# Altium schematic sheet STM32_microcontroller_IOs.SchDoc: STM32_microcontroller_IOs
size A3; Date: Not used; ApprovedBy: Not used; CheckedBy: Not used; Author: Not used; CompanyName: STMicroelectronics; DrawnBy: Not used; Engineer: Not used; Organization: Not used; Address1: Not used; Address2: Not used; Address3: Not used; Address4: Not used; DocumentNumber: Not used; Revision: Not used; SheetNumber: 3; SheetTotal: 12
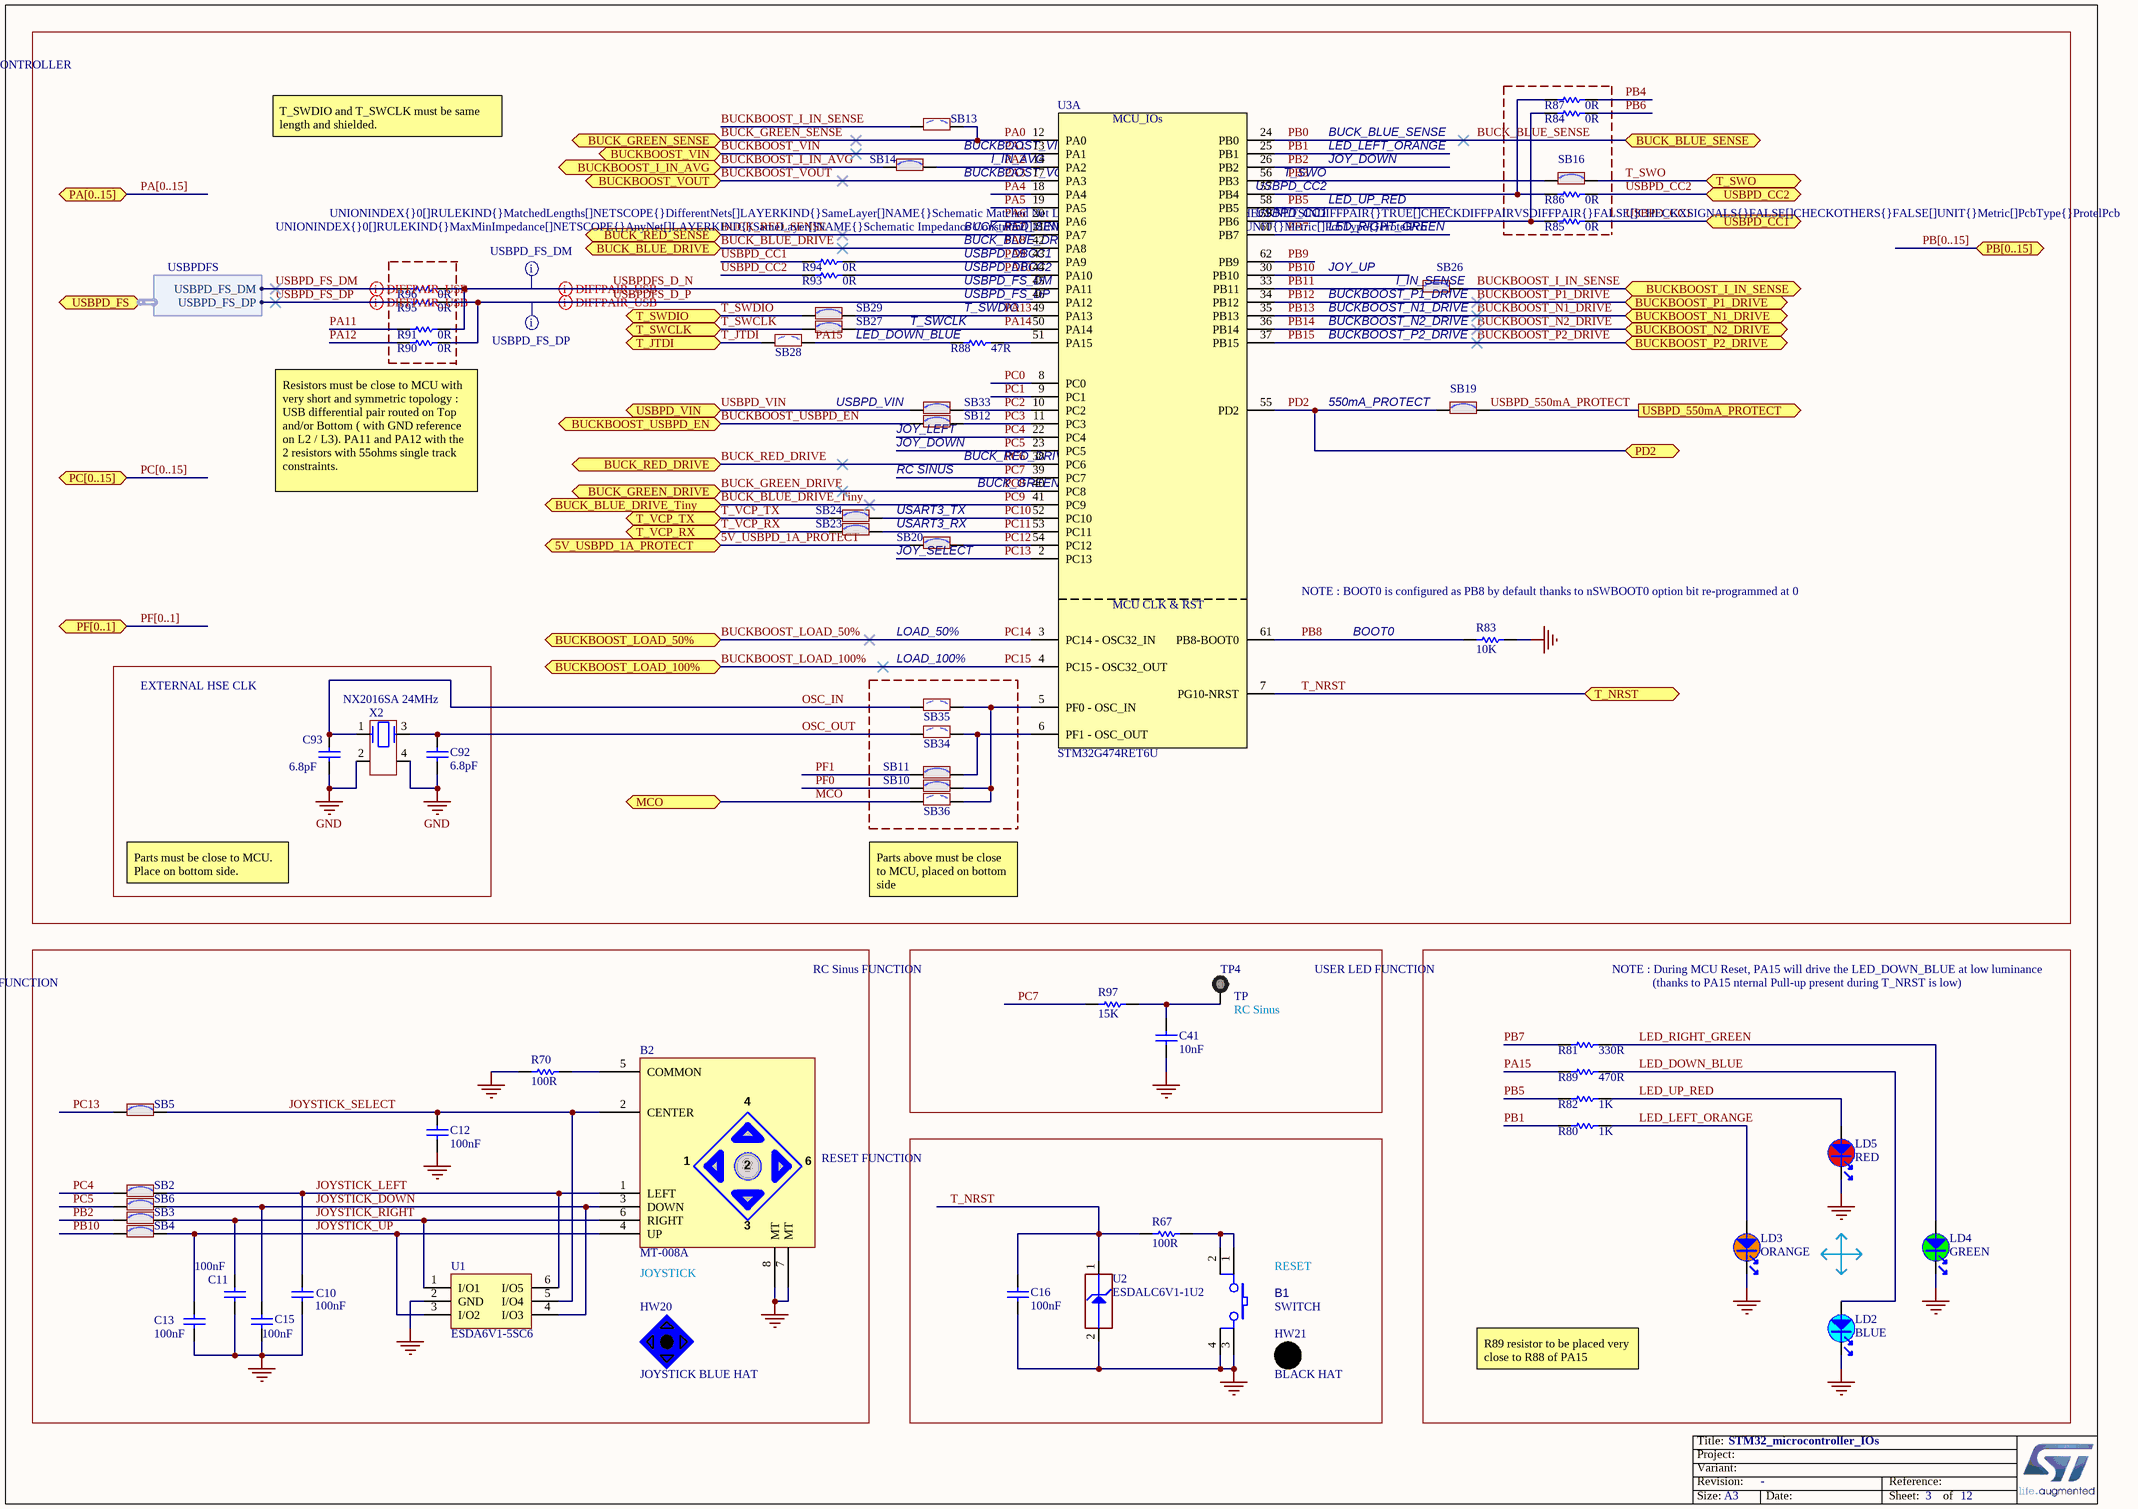
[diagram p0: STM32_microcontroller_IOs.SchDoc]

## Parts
B1  value SWITCH  [SWI_WEALTHMETAL_TD-0341_4P_BLACK]
B2  value MT-008A  [SWI_XIEJIA_MT-008A_6P]
C10  value 100nF  [C0402]
C11  value 100nF  [C0402]
C12  value 100nF  [C0402]
C13  value 100nF  [C0402]
C15  value 100nF  [C0402]
C16  value 100nF  [C0402]
C41  value 10nF  [C0603]
C92  value 6.8pF  [C0402]
C93  value 6.8pF  [C0402]
HW20  value JOYSTICK BLUE HAT  (hidden comment: JOYSTICK_BLUE_HAT)  (mechanical)
HW21  value BLACK HAT  (mechanical)
LD2  value BLUE  [LED_0603_SMD-B_BLUE_H0P4]
LD3  value ORANGE  [LED_0603_ORANGE_H0P4]
LD4  value GREEN  [LED_0603_GREEN]
LD5  value RED  [LED_0603_RED]
R67  value 100R  [R0603]
R70  value 100R  [R0603]
R80  value 1K  [R0603]
R81  value 330R  [R0603]
R82  value 1K  [R0603]
R83  value 10K  [R0603]
R84  value 0R  [R0402]
R85  value 0R  [R0402]
R86  value 0R  [R0402]
R87  value 0R  [R0402]
R88  value 47R  [R0402]
R89  value 470R  [R0603]
R90  value 0R  [R0402]
R91  value 0R  [R0402]
R93  value 0R  [R0402]
R94  value 0R  [R0402]
R95  value 0R  [R0402]
R96  value 0R  [R0402]
R97  value 15K  [R0603]
SB2  (no value)  [SOLDER-BRIDGE_R0603-0R]
SB3  (no value)  [SOLDER-BRIDGE_R0603-0R]
SB4  (no value)  [SOLDER-BRIDGE_R0603-0R]
SB5  (no value)  [SOLDER-BRIDGE_R0603-0R]
SB6  (no value)  [SOLDER-BRIDGE_R0603-0R]
SB10  (no value)  [SOLDER-BRIDGE_R0603-0R]
SB11  (no value)  [SOLDER-BRIDGE_R0603-0R]
SB12  (no value)  [SOLDER-BRIDGE_R0603-0R]
SB13  (no value)  [SOLDER-BRIDGE_R0603-0R]
SB14  (no value)  [SOLDER-BRIDGE_R0603-0R]
SB16  (no value)  [SOLDER-BRIDGE_R0603-0R]
SB19  (no value)  [SOLDER-BRIDGE_R0603-0R]
SB20  (no value)  [SOLDER-BRIDGE_R0603-0R]
SB23  (no value)  [SOLDER-BRIDGE_R0603-0R]
SB24  (no value)  [SOLDER-BRIDGE_R0603-0R]
SB26  (no value)  [SOLDER-BRIDGE_R0603-0R]
SB27  (no value)  [SOLDER-BRIDGE_R0603-0R]
SB28  (no value)  [SOLDER-BRIDGE_R0603-0R]
SB29  (no value)  [SOLDER-BRIDGE_R0603-0R]
SB33  (no value)  [SOLDER-BRIDGE_R0603-0R]
SB34  (no value)  [SOLDER-BRIDGE_R0603-0R]
SB35  (no value)  [SOLDER-BRIDGE_R0603-0R]
SB36  (no value)  [SOLDER-BRIDGE_R0603-0R]
TP4  value TP  [TP_PTH_1MM_2MM]
U1  value ESDA6V1-5SC6  [ESD_SOT23-6L]
U2  value ESDALC6V1-1U2  [ESD_ST0201]
U3  STM32G474RET6U  [ICC_LQFP64_10X10_P050]  (part A of 2)
X2  value NX2016SA 24MHz  [CRY_NX2016SA_4P]

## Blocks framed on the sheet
EXTERNAL HSE CLK: C92 C93 X2
LOAD_100%: SB10 SB11 SB34-SB36
USER LED FUNCTION: LD2-LD5 R80-R82 R89

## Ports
5V_USBPD_1A_PROTECT, BUCK_BLUE_DRIVE, BUCK_BLUE_DRIVE_Tiny, BUCK_BLUE_SENSE, BUCK_GREEN_DRIVE, BUCK_GREEN_SENSE, BUCK_RED_DRIVE, BUCK_RED_SENSE, BUCKBOOST_I_IN_AVG, BUCKBOOST_I_IN_SENSE, BUCKBOOST_LOAD_50%, BUCKBOOST_LOAD_100%, BUCKBOOST_N1_DRIVE, BUCKBOOST_N2_DRIVE, BUCKBOOST_P1_DRIVE, BUCKBOOST_P2_DRIVE, BUCKBOOST_USBPD_EN, BUCKBOOST_VIN, BUCKBOOST_VOUT, MCO, PA[0..15] (bidir), PB[0..15] (bidir), PC[0..15] (bidir), PD2, PF[0..1] (bidir), T_JTDI, T_NRST, T_SWCLK, T_SWDIO, T_SWO, T_VCP_RX, T_VCP_TX, USBPD_550mA_PROTECT, USBPD_CC1, USBPD_CC2, USBPD_FS (harness USBPDFS), USBPD_VIN

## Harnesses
USBPDFS: USBPD_FS_DM, USBPD_FS_DP

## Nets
GND: B1.3 B1.4 B2.7(MT) B2.8(MT) C10.1 C11.1 C12.1 C13.1 C15.1 C16.1 C41.1 C92.1 C93.1 LD2.2 LD3.2 LD4.2 LD5.2 R70.1 R83.1 U1.2(GND) U2.2(GND) X2.2 X2.4
5V_USBPD_1A_PROTECT: SB20.1 ; port 5V_USBPD_1A_PROTECT
BUCK_BLUE_DRIVE: U3.42(PA8) ; port BUCK_BLUE_DRIVE  [also labelled PA8]
BUCK_BLUE_DRIVE_Tiny: U3.41(PC9) ; port BUCK_BLUE_DRIVE_Tiny  [also labelled PC9]
BUCK_BLUE_SENSE: U3.24(PB0) ; port BUCK_BLUE_SENSE  [also labelled PB0]
BUCK_GREEN_DRIVE: U3.40(PC8) ; port BUCK_GREEN_DRIVE  [also labelled PC8]
BUCK_GREEN_SENSE: SB13.2 U3.12(PA0) ; port BUCK_GREEN_SENSE  [also labelled PA0]
BUCK_RED_DRIVE: U3.38(PC6) ; port BUCK_RED_DRIVE  [also labelled PC6]
BUCK_RED_SENSE: U3.21(PA7) ; port BUCK_RED_SENSE  [also labelled PA7]
BUCKBOOST_I_IN_AVG: SB14.1 ; port BUCKBOOST_I_IN_AVG
BUCKBOOST_I_IN_SENSE: SB13.1 SB26.2 ; port BUCKBOOST_I_IN_SENSE
BUCKBOOST_LOAD_50%: U3.3(PC14_-_OSC32_IN) ; port BUCKBOOST_LOAD_50%  [also labelled PC14]
BUCKBOOST_LOAD_100%: U3.4(PC15_-_OSC32_OUT) ; port BUCKBOOST_LOAD_100%  [also labelled PC15]
BUCKBOOST_N1_DRIVE: U3.35(PB13) ; port BUCKBOOST_N1_DRIVE  [also labelled PB13]
BUCKBOOST_N2_DRIVE: U3.36(PB14) ; port BUCKBOOST_N2_DRIVE  [also labelled PB14]
BUCKBOOST_P1_DRIVE: U3.34(PB12) ; port BUCKBOOST_P1_DRIVE  [also labelled PB12]
BUCKBOOST_P2_DRIVE: U3.37(PB15) ; port BUCKBOOST_P2_DRIVE  [also labelled PB15]
BUCKBOOST_USBPD_EN: SB12.1 ; port BUCKBOOST_USBPD_EN
BUCKBOOST_VIN: U3.13(PA1) ; port BUCKBOOST_VIN  [also labelled PA1]
BUCKBOOST_VOUT: U3.17(PA3) ; port BUCKBOOST_VOUT  [also labelled PA3]
JOYSTICK_DOWN: B2.3(DOWN) C15.2 SB6.2 U1.4(I/O3)
JOYSTICK_LEFT: B2.1(LEFT) C10.2 SB2.1 U1.6(I/O5)
JOYSTICK_RIGHT: B2.6(RIGHT) C11.2 SB3.1 U1.1(I/O1)
JOYSTICK_SELECT: B2.2(CENTER) C12.2 SB5.2 U1.5(I/O4)
JOYSTICK_UP: B2.4(UP) C13.2 SB4.1 U1.3(I/O2)
LED_DOWN_BLUE: LD2.1 R89.2
LED_LEFT_ORANGE: LD3.1 R80.1
LED_RIGHT_GREEN: LD4.1 R81.1
LED_UP_RED: LD5.1 R82.1
MCO: SB36.1 ; port MCO
OSC_IN: C93.2 SB35.1 X2.1
OSC_OUT: C92.2 SB34.1 X2.3
PA2: SB14.2 U3.14(PA2)
PA4: U3.18(PA4)
PA5: U3.19(PA5)
PA6: U3.20(PA6)
PA9: R94.2 U3.43(PA9)
PA10: R93.2 U3.44(PA10)
PA11: R91.1
PA12: R90.1
PA13: SB29.2 U3.49(PA13)
PA14: SB27.2 U3.50(PA14)
PA15: R88.1 R89.1 SB28.2
PB1: R80.2 U3.25(PB1)
PB2: SB3.2 U3.26(PB2)
PB3: SB16.1 U3.56(PB3)
PB4: R87.2
PB5: R82.2 U3.58(PB5)
PB6: R84.2
PB7: R81.2 U3.60(PB7)
PB8: R83.2 U3.61(PB8-BOOT0)
PB9: U3.62(PB9)
PB10: SB4.2 U3.30(PB10)
PB11: SB26.1 U3.33(PB11)
PC0: U3.8(PC0)
PC1: U3.9(PC1)
PC2: SB33.2 U3.10(PC2)
PC3: SB12.2 U3.11(PC3)
PC4: SB2.2 U3.22(PC4)
PC5: SB6.1 U3.23(PC5)
PC7: R97.1 U3.39(PC7)
PC10: SB24.2 U3.52(PC10)
PC11: SB23.2 U3.53(PC11)
PC12: SB20.2 U3.54(PC12)
PC13: SB5.1 U3.2(PC13)
PD2: SB19.1 U3.55(PD2) ; port PD2
PF0: SB10.1
PF1: SB11.1
T_JTDI: SB28.1 ; port T_JTDI
T_NRST: C16.2 R67.1 U2.1(IO1) U3.7(PG10-NRST) ; port T_NRST
T_SWCLK: SB27.1 ; port T_SWCLK
T_SWDIO: SB29.1 ; port T_SWDIO
T_SWO: SB16.2 ; port T_SWO
T_VCP_RX: SB23.1 ; port T_VCP_RX
T_VCP_TX: SB24.1 ; port T_VCP_TX
USBPD_550mA_PROTECT: SB19.2 ; port USBPD_550mA_PROTECT
USBPD_CC1: R85.2 R94.1 ; port USBPD_CC1
USBPD_CC2: R86.2 R93.1 ; port USBPD_CC2
USBPD_FS_DM: R96.1 ; port USBPD_FS.USBPD_FS_DM
USBPD_FS_DP: R95.1 ; port USBPD_FS.USBPD_FS_DP
USBPD_VIN: SB33.1 ; port USBPD_VIN
USBPDFS_D_N: R91.2 R96.2 U3.45(PA11)
USBPDFS_D_P: R90.2 R95.2 U3.46(PA12)
NetB1_1: B1.1 B1.2 R67.2
NetB2_5: B2.5(COMMON) R70.2
NetC41_2: C41.2 R97.2 TP4.1
NetR84_1: R84.1 R85.1 U3.59(PB6)
NetR86_1: R86.1 R87.1 U3.57(PB4)
NetR88_2: R88.2 U3.51(PA15)
NetSB10_2: SB10.2 SB35.2 SB36.2 U3.5(PF0_-_OSC_IN)
NetSB11_2: SB11.2 SB34.2 U3.6(PF1_-_OSC_OUT)

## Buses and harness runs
bus PA[0..15] = port PA[0..15]
bus PB[0..15] = port PB[0..15]
bus PC[0..15] = port PC[0..15]
bus PF[0..1] = port PF[0..1]

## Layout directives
differential pair; rule Impedance Constraint [Min = 85.00    Max = 95.00    ]: USBPD_FS_DM, USBPD_FS_DP, USBPDFS_D_N, USBPDFS_D_P
rule Undefined; rule Matched Net Lengths [Tolerance = 0.2mm]; rule Impedance Constraint [Min = 85.00    Max = 95.00    ]: USBPDFS_D_N, USBPDFS_D_P

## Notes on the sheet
- MICROCONTROLLER
- T_SWDIO and T_SWCLK must be same length and shielded.
- BUCKBOOST_VIN
- (near SB14) BUCKBOOST_VOUT
- I_IN_AVG
- T_SWO
- LED_LEFT_ORANGE
- JOY_DOWN
- BUCK_BLUE_SENSE
- BUCK_RED_SENSE
- BUCK_BLUE_DRIVE
- USBPD_CC2
- USBPD_CC1
- LED_UP_RED
- LED_RIGHT_GREEN
- (near R88) T_SWDIO
- USBPD_DBCC1
- USBPD_DBCC2
- USBPD_FS_DM
- USBPD_FS_DP
- JOY_UP
- (near SB26) BUCKBOOST_P1_DRIVE
- (near SB26) BUCKBOOST_N1_DRIVE
- (near SB26) I_IN_SENSE
- LED_DOWN_BLUE
- (near R88) T_SWCLK
- (near SB26) BUCKBOOST_P2_DRIVE
- (near SB26) BUCKBOOST_N2_DRIVE
- USBPD_VIN
- (near SB12) JOY_LEFT
- (near SB12) JOY_DOWN
- (near SB19) 550mA_PROTECT
- Resistors must be close to MCU with very short and symmetric topology : USB differential pair routed on Top and/or Bottom ( with GND reference on L2 / L3). PA11 and PA12 with the 2 resistors with 55ohms single track constraints.
- USART3_TX
- RC SINUS
- BUCK_RED_DRIVE
- BUCK_GREEN_DRIVE
- (near SB20) USART3_RX
- (near SB20) JOY_SELECT
- LOAD_50%
- NOTE : BOOT0 is configured as PB8 by default thanks to nSWBOOT0 option bit re-programmed at 0
- (near R83) BOOT0
- Parts must be close to MCU. Place on bottom side.
- Parts above must be close to MCU, placed on bottom side
- JOYSTICK FUNCTION
- RC Sinus FUNCTION
- NOTE : During MCU Reset, PA15 will drive the LED_DOWN_BLUE at low luminance
- (thanks to PA15 nternal Pull-up present during T_NRST is low)
- (near TP4) RC Sinus
- RESET FUNCTION
- JOYSTICK
- (near B1) RESET
- R89 resistor to be placed very close to R88 of PA15

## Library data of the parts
B1 = MCD-00001: Non-Open Push-Button 0.1A 24V BLACK; Manufacturer_Part_Number: TD-0341; Manufacturer: WEALTHMETAL; Part_Type: Misc; Provided_By: SUBCO
B2 = MCD-00132: Joystick, 4 dir, 1 OK; Part_Type: Misc; Manufacturer: XIEJIA Electronics; Provided_By: SUBCO
C10-C13 C15 C16 = MCD-00102: Capacitor, MLCC, 100nF, 16V, X7R, 10%, 0402, T=0,5mm; Manufacturer_Part_Number: CC0402KRX7R7BB104; Manufacturer: YAGEO; Alternate_Manufacturer_Part_Number: GCM155R71C104KA55D; Alternate_Manufacturer: MURATA; Provided_By: SUBCO
C41 = MCD-01007: Capacitor, MLCC, 10nF, 16V, X7R, 10%, 0603, T=0.8mm; Manufacturer_Part_Number: CC0603KRX7R7BB103; Manufacturer: YAGEO; Provided_By: SUBCO
C92 C93 = MCD-00674: Capacitor, MLCC, 6.8pF, 50V, NPO, +-0.25pF, 0402, T=0.5mm; Manufacturer_Part_Number: CC0402CRNPO9BN6R8; Manufacturer: YAGEO; Provided_By: SUBCO
HW20 = MCD-01337: Joystick Blue Hat; Part_Type: Mechanical; Manufacturer_Part_Number: PB-504; Manufacturer: JIUBABA; Provided_By: SUBCO
HW21 = MCD-00635: Black Hat for switch TD0341X-G01-BLA; Part_Type: Mechanical; Manufacturer_Part_Number: 988.16.09.3.00003_SH-517; Manufacturer: JIUBABA; Provided_By: SUBCO
LD2 = MCD-01131: LED Blue, 0603 SMD, Forward Voltage Min=2,8V, Max=3,1V; Part_Type: Display; Manufacturer_Part_Number: 19-217-BHC-ZL1M2RY-3T; Manufacturer: EVERLIGHT; Provided_By: SUBCO
LD3 = MCD-00321: LED, Orange, 0603; Part_Type: Display; Manufacturer_Part_Number: 19-217/S2C-AM2N2VY/3T; Manufacturer: EVERLIGHT; Provided_By: SUBCO
LD4 = MCD-00050: LED, Green, 0603; Manufacturer_Part_Number: 19-213SYGC/S530-E2/TR8; Manufacturer: EVERLIGHT; Part_Type: Display; Provided_By: SUBCO
LD5 = MCD-00049: LED, Red, 0603; Part_Type: Display; Manufacturer_Part_Number: 19-213-R6C-AP1Q2B/3T; Manufacturer: EVERLIGHT; Provided_By: SUBCO
R67 R70 = MCD-00224: Resistor,100R,0603,1%,1/10W; Manufacturer_Part_Number: RC0603FR-07100RL; Manufacturer: YAGEO; Provided_By: SUBCO
R80 R82 = MCD-00070: Resistor,1K,0603,1%,1/10W; Manufacturer_Part_Number: RC0603FR-071KL; Manufacturer: YAGEO; Provided_By: SUBCO
R81 = MCD-00197: Resistor,330R,0603,1%,1/10W; Manufacturer_Part_Number: RC0603FR-07330RL; Manufacturer: YAGEO; BMS_Part_Number: 9129729; Provided_By: SUBCO
R83 = MCD-00220: Resistor,10K,0603,1%,1/10W; Manufacturer_Part_Number: RC0603FR-0710KL; Manufacturer: YAGEO; Provided_By: SUBCO
R84-R87 R90 R91 R93-R96 = MCD-00052: Resistor,0R,0402,5%,1/16W; Manufacturer_Part_Number: RC0402JR-070RL; Manufacturer: YAGEO; Provided_By: SUBCO
R88 = MCD-00481: Resistor,47R,0402,1%,1/16W; Manufacturer_Part_Number: RC0402FR-0747RL; Manufacturer: YAGEO; Provided_By: SUBCO
R89 = MCD-00354: Resistor,470R,0603,1%,1/10W; Manufacturer_Part_Number: RC0603FR-07470RL; Manufacturer: YAGEO; BMS_Part_Number: 9129906; Provided_By: SUBCO
R97 = MCD-00341: Resistor,15K,0603,1%,1/10W; Manufacturer_Part_Number: RC0603FR-0715KL; Manufacturer: YAGEO; Provided_By: SUBCO
SB2-SB6 SB10-SB12 SB14 SB16 SB19 SB20 SB23 SB24 SB26 SB27 SB29 SB33 = MCD-00071: Solder Bridge ON; Part_Type: Mechanical; Manufacturer_Part_Number: RC0603JR-070RL; Manufacturer: YAGEO; Provided_By: SUBCO
SB13 SB28 SB34-SB36 = MCD-00072: Solder Bridge OFF; Part_Type: Mechanical; Manufacturer_Part_Number: RC0603JR-070RL; Manufacturer: YAGEO; Provided_By: SUBCO
TP4 = MCD-01506: Test Point trought hole 1mm/2mm; Part_Type: Mechanical
U1 = MCD-01066: 5 unidirectional Transil diodes ESD protection; Part_Type: Diode; Manufacturer: STMICROELECTRONICS; BMS_Part_Number: 9179044; Provided_By: SUBCO with ST control
U2 = MCD-00170: ESD protection 6V1; Part_Type: Diode; Manufacturer: STMICROELECTRONICS; BMS_Part_Number: 9151132; Provided_By: SUBCO with ST control
U3 = MCD-01584: STM32G474RET6U MCU, LQFP64 10x10, 1.6, 512KB Flash, 128KB SRAM; Part_Type: IC; Manufacturer: STMICROELECTRONICS; ECCN_US: 3A991A2; ECCN_EU: NEC; Provided_By: SUBCO with ST control
X2 = MCD-01036: Crystal 24MHz, 6pF, +-20ppm, 80ohms max, SMD; Part_Type: Crystal_Osc; Manufacturer_Part_Number: NX2016SA 24MHz EXS00A-CS10820; Manufacturer: NDK; BMS_Part_Number: 9157045; Provided_By: SUBCO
